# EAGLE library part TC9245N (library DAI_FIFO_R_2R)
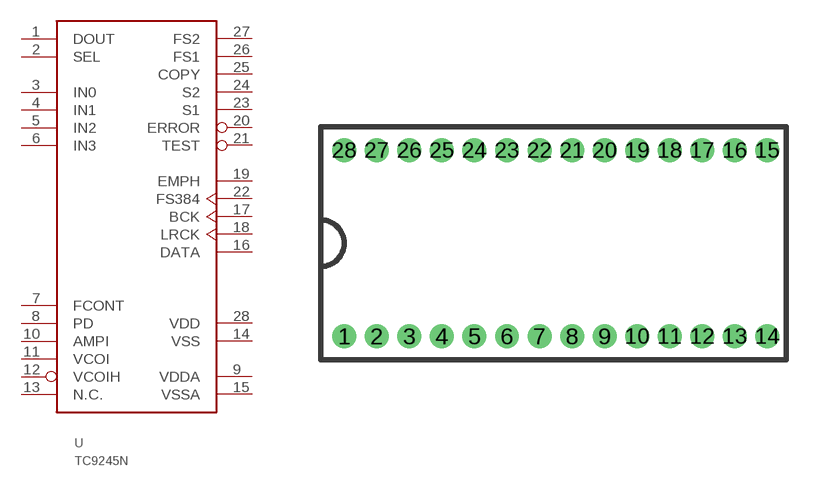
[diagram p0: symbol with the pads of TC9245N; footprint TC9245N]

Designator prefix U

## TC9245N  [TC9245N]
1  DOUT  out
2  SEL  in
3  IN0  in
4  IN1  in
5  IN2  in
6  IN3  in
7  FCONT  out
8  PD  out
9  VDDA  pwr
10  AMPI  in
11  VCOI  out
12  VCOIH  nc
13  N.C.  nc
14  VSS  pwr
15  VSSA  pwr
16  DATA  out
17  BCK  out
18  LRCK  out
19  EMPH  out
20  ERROR  out
21  TEST  out
22  FS384  out
23  S1  in
24  S2  in
25  COPY  out
26  FS1  out
27  FS2  out
28  VDD  pwr

## Footprint TC9245N (pad centres in mm)
drill 0.8 pad 1.27 round: 1 0,0; 2 1.778,0; 3 3.556,0; 4 5.334,0; 5 7.112,0; 6 8.89,0; 7 10.668,0; 8 12.446,0; 9 14.224,0; 10 16.002,0; 11 17.78,0; 12 19.558,0; 13 21.336,0; 14 23.114,0; 15 23.114,10.16; 16 21.336,10.16; 17 19.558,10.16; 18 17.78,10.16; 19 16.002,10.16; 20 14.224,10.16; 21 12.446,10.16; 22 10.668,10.16; 23 8.89,10.16; 24 7.112,10.16; 25 5.334,10.16; 26 3.556,10.16; 27 1.778,10.16; 28 0,10.16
